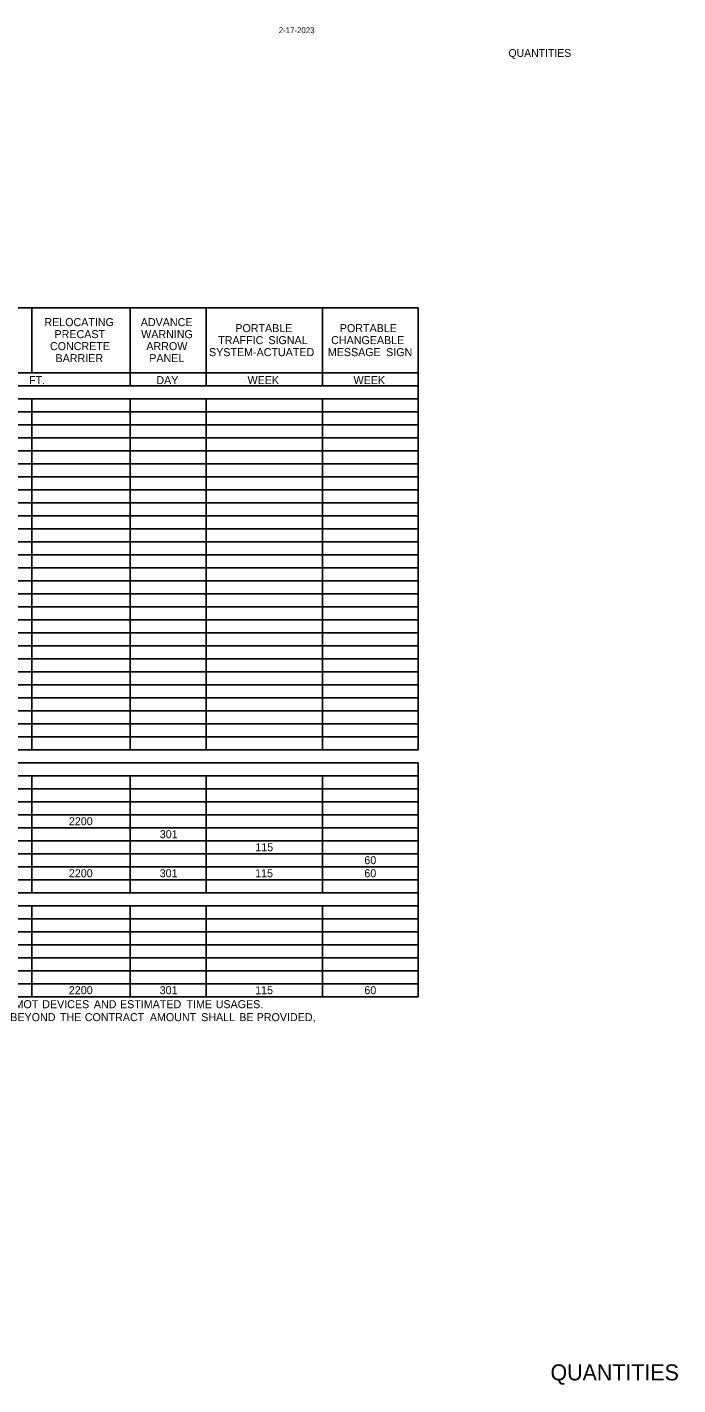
# Model space of a CAD drawing. Extents: x 544255 to 1930787, y -1947044 to 596640.
# Drawn here: x 549101 to 549589, y -1947044 to -1946026 of the extents above; entities that cross this region are included whole.
import ezdxf

# ---------------------------------------------------------------- set-up
doc = ezdxf.new("R2010")
doc.units = 0
for name, color, linetype in [('Default', 7, 'Continuous'), ('R_Border', 7, 'Continuous'), ('R_Border Prem', 7, 'Continuous')]:
    doc.layers.add(name, color=color, linetype=linetype)

msp = doc.modelspace()

# ---------------------------------------------------------------- linework, layer by layer
at = {"layer": 'Default'}
for p, q in [((548283.3, -1946236.5), (549393.9, -1946236.5)), ((549104.3, -1946285.2), (549104.3, -1946236.5)), ((549177.9, -1946295), (549177.9, -1946236.5)), ((549234.9, -1946295), (549234.9, -1946236.5)), ((549322.2, -1946236.5), (549393.9, -1946236.5)), ((549322.2, -1946295), (549322.2, -1946236.5)), ((549393.9, -1946568), (549393.9, -1946236.5)), ((549393.9, -1946568), (549393.9, -1946236.5)), ((548809.8, -1946285.2), (549393.9, -1946285.2)), ((549322.2, -1946295), (549322.2, -1946285.2)), ((548283.3, -1946295), (549393.9, -1946295)), ((548751.8, -1946295), (549393.9, -1946295)), ((548283.3, -1946304.7), (549393.9, -1946304.7)), ((549104.3, -1946568), (549104.3, -1946304.7)), ((549104.3, -1946568), (549104.3, -1946304.7)), ((549177.9, -1946568), (549177.9, -1946304.7)), ((549177.9, -1946568), (549177.9, -1946304.7)), ((549234.9, -1946568), (549234.9, -1946304.7)), ((549322.2, -1946568), (549322.2, -1946304.7)), ((548283.3, -1946314.5), (549393.9, -1946314.5)), ((548283.3, -1946324.2), (549393.9, -1946324.2)), ((548283.3, -1946334), (549393.9, -1946334)), ((548283.3, -1946343.7), (549393.9, -1946343.7)), ((548283.3, -1946353.5), (549393.9, -1946353.5)), ((548283.3, -1946363.2), (549393.9, -1946363.2)), ((548283.3, -1946373), (549393.9, -1946373)), ((548283.3, -1946382.7), (549393.9, -1946382.7)), ((548283.3, -1946392.5), (549393.9, -1946392.5)), ((548283.3, -1946402.2), (549393.9, -1946402.2)), ((548283.3, -1946412), (549393.9, -1946412)), ((548283.3, -1946421.7), (549393.9, -1946421.7)), ((548283.3, -1946431.5), (549393.9, -1946431.5)), ((548283.3, -1946441.2), (549393.9, -1946441.2)), ((548283.3, -1946451), (549393.9, -1946451)), ((548283.3, -1946460.7), (549393.9, -1946460.7)), ((548283.3, -1946470.5), (549393.9, -1946470.5)), ((548283.3, -1946480.2), (549393.9, -1946480.2)), ((548283.3, -1946490), (549393.9, -1946490)), ((548283.3, -1946499.7), (549393.9, -1946499.7)), ((548283.3, -1946509.5), (549393.9, -1946509.5)), ((548283.3, -1946519.2), (549393.9, -1946519.2)), ((548283.3, -1946529), (549393.9, -1946529)), ((548283.3, -1946538.7), (549393.9, -1946538.7)), ((548283.3, -1946548.5), (549393.9, -1946548.5)), ((548283.3, -1946558.2), (549393.9, -1946558.2)), ((548283.3, -1946558.2), (549393.9, -1946558.2)), ((549234.9, -1946568), (549234.9, -1946558.2)), ((549322.2, -1946568), (549322.2, -1946558.2)), ((548283.3, -1946568), (549393.9, -1946568)), ((548283.3, -1946577.7), (549393.9, -1946577.7)), ((548283.3, -1946577.7), (549393.9, -1946577.7)), ((549393.9, -1946753.2), (549393.9, -1946577.7)), ((549393.9, -1946753.2), (549393.9, -1946577.7)), ((548283.3, -1946587.5), (549393.9, -1946587.5)), ((549104.3, -1946675.2), (549104.3, -1946587.5)), ((549104.3, -1946675.2), (549104.3, -1946587.5)), ((549177.9, -1946607), (549177.9, -1946587.5)), ((549177.9, -1946675.2), (549177.9, -1946587.5)), ((549234.9, -1946675.2), (549234.9, -1946587.5)), ((549322.2, -1946675.2), (549322.2, -1946587.5)), ((548283.3, -1946597.2), (549393.9, -1946597.2)), ((548283.3, -1946607), (549393.9, -1946607)), ((548283.3, -1946616.7), (549393.9, -1946616.7)), ((549020.9, -1946616.7), (549393.9, -1946616.7)), ((549177.9, -1946675.2), (549177.9, -1946616.7)), ((548283.3, -1946626.5), (549393.9, -1946626.5)), ((548283.3, -1946636.2), (549393.9, -1946636.2)), ((548283.3, -1946646), (549393.9, -1946646)), ((549234.9, -1946675.2), (549234.9, -1946646)), ((549322.2, -1946655.7), (549322.2, -1946646)), ((548283.3, -1946655.7), (549393.9, -1946655.7)), ((548809.8, -1946655.7), (549393.9, -1946655.7)), ((548283.3, -1946665.5), (549393.9, -1946665.5)), ((548283.3, -1946675.2), (549393.9, -1946675.2)), ((548283.3, -1946685), (549393.9, -1946685)), ((549104.3, -1946753.2), (549104.3, -1946685)), ((549177.9, -1946753.2), (549177.9, -1946685)), ((549234.9, -1946753.2), (549234.9, -1946685)), ((549322.2, -1946753.2), (549322.2, -1946685)), ((548283.3, -1946694.7), (549393.9, -1946694.7)), ((548283.3, -1946704.5), (549393.9, -1946704.5)), ((548283.3, -1946714.2), (549393.9, -1946714.2)), ((548283.3, -1946724), (549393.9, -1946724)), ((548910.3, -1946724), (549393.9, -1946724)), ((549104.3, -1946753.2), (549104.3, -1946724)), ((549177.9, -1946753.2), (549177.9, -1946724)), ((549234.9, -1946753.2), (549234.9, -1946724)), ((548283.3, -1946733.7), (549393.9, -1946733.7)), ((548283.3, -1946743.5), (549393.9, -1946743.5)), ((548283.3, -1946753.2), (549393.9, -1946753.2))]:
    msp.add_line(p, q, dxfattribs=at)

# ---------------------------------------------------------------- texts
for s, p in [('RELOCATING', (549113.6, -1946250.3)), ('ADVANCE', (549185.9, -1946250.3)), ('PRECAST', (549121.2, -1946259.3)), ('WARNING', (549186.2, -1946259.3)), (' PORTABLE', (549254.6, -1946254.8)), ('PORTABLE', (549335.2, -1946254.8)), ('CONCRETE', (549117.8, -1946268.3)), ('ARROW', (549190.1, -1946268.3)), ('SYSTEM-ACTUATED', (549237.1, -1946272.8)), ('TRAFFIC', (549244, -1946263.8)), (' SIGNAL', (549279.4, -1946263.8)), ('MESSAGE', (549326.2, -1946272.8)), ('CHANGEABLE', (549328.7, -1946263.8)), (' SIGN', (549367.7, -1946272.8)), ('BARRIER', (549122, -1946277.3)), ('PANEL', (549192.3, -1946277.3)), (' FT.', (549099.9, -1946293.8)), ('DAY', (549197.6, -1946293.8)), ('WEEK', (549266, -1946293.8)), ('WEEK', (549345.5, -1946293.8)), ('2200', (549132, -1946624.6)), ('301', (549200.2, -1946634.3)), ('115', (549271.8, -1946644.1)), ('60', (549353.6, -1946653.8)), ('2200', (549132, -1946663.6)), ('301', (549200.1, -1946663.6)), ('115', (549271.7, -1946663.6)), ('60', (549353.6, -1946663.6)), ('2200', (549132, -1946751.3)), ('301', (549200.1, -1946751.3)), ('115', (549271.7, -1946751.3)), ('60', (549353.6, -1946751.3)), (' MOT', (549089, -1946761.8)), (' DEVICES', (549109.8, -1946761.8)), (' AND', (549148.5, -1946761.8)), (' ESTIMATED', (549168.1, -1946761.8)), (' TIME', (549218, -1946761.8)), (' USAGES.', (549239.9, -1946761.8)), (' BEYOND', (549085.8, -1946771.5)), (' THE', (549123.1, -1946771.5)), (' CONTRACT', (549141.7, -1946771.5)), (' AMOUNT', (549190.5, -1946771.5)), (' SHALL', (549229, -1946771.5)), (' BE', (549257.6, -1946771.5)), (' PROVIDED,', (549270.6, -1946771.5))]:
    msp.add_text(s, height=6, dxfattribs=at).set_placement(p)
at = {"layer": 'R_Border'}
msp.add_text('QUANTITIES', height=12, rotation=360, dxfattribs=at).set_placement((549493.2, -1947040.9))
at = {"layer": 'R_Border Prem'}
msp.add_text('2-17-2023', height=4.4, dxfattribs=at).set_placement((549289.4, -1946030.6))
msp.add_text('QUANTITIES', height=5.86, rotation=360, dxfattribs=at).set_placement((549461.7, -1946048.4))

doc.saveas('drawing.dxf')
